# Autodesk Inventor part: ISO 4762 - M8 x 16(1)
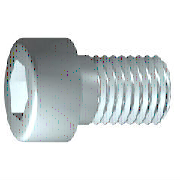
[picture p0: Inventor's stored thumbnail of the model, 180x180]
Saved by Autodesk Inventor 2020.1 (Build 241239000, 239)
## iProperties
Created: 2019-01
Part Number: ISO 4762 - M8 x 16(1)
Material: Edelstahl, 440C
Description: Innensechskantschraube
Document SubType Name: Modeling
Standard: ISO 4762
Designer: lutzd
Standard Revision: Fourth edition 2004-03-01
Standards Organization: ISO
Language: de-DE
Size Designation: M8 x 16
Categories: <MemberInstance><Categories><Category DisplayName="Verbindungselemente" InternalName="e4da775c-781d-43d5-af7c-5136215cf5a6" Mnemonic="FSTN"><Category DisplayNam
Mass: 13.2109 g
Surface Area: 10.585 cm^2
Volume: 1.70464 cm^3
Density: 7.75 g/cm^3
Appearance: Halbpoliert
IsCustomPart: 0
Author: lutzd
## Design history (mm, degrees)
body "Solid1"
sketch "Skizze1"
  geometry: L1 (-2, 0)-(16, 0); L2 (16, 0)-(16, 4); L3 (16, 4)-(3.125, 4); L4 (3.125, 4)-(2.358, 4); L5 (2.358, 4)-(0, 4); L6 (0, 4)-(0, 6.5); L7 (0, 6.5)-(-8, 6.5); L8 (-8, 6.5)-(-8, 3.464); L9 (-8, 3.464)-(-4, 3.464); L10 (-4, 3.464)-(-2, 0); L11 (-12.8, 0)-(20.8, 0) reference; L12 (0, -1.3)-(0, 7.8) reference; L13 (3.125, 4)-(0, 4)
  constraints: 22 end point, 6 parallel, 2 collinear, 2 perpendicular, 1 horizontal, 1 point on line
  dimensions: "d1" = 12.875 distance from line of L3.end L2 (= GEL); "d2" = 0.76691 distance of L4.end L3.end (computed from GAL); "d3" = 8 distance between parallel lines of L8 L6 (= KOH); "d4" = 4 distance of L8.end L9.end (= INTI); "d5" = 60 deg angle of L10 L1; "d6" = 8 diameter of L3 L1 (= GD); "d7" = 8 diameter of L5 L1 (= BDM); "d8" = 6.9282 diameter of L9 L1 (= 1.1547 x SW); "d9" = 13 diameter of L7 L1 (= KOD); "d26" = 16 distance between parallel lines of L12 L2 (= NLG)
workplane "Work Plane1"
fillet "Fillet2" dims "d30" = 0.1 (= R)
revolve "Körper" stored, may be unused: angle "d10" = 90 deg
sketch "Skizze2"
  geometry: L1 (0, -9.1)-(0, 9.1) reference; L2 (-9.1, 0)-(9.1, 0) reference; L3 (3.464, 0)-(1.732, -3); L4 (1.732, -3)-(-1.732, -3); L5 (-1.732, -3)-(-3.464, 0); L6 (-3.464, 0)-(-1.732, 3); L7 (-1.732, 3)-(1.732, 3); L8 (1.732, 3)-(3.464, 0); 2 further points
  constraints: 12 end point, 1 coincident, 1 horizontal alignment, 1 point on line, 12 other
extrude "Loch" join sketch "Skizze2" stored distance "d11" = 10; taper "d12" = 0 deg
fillet "Rundung1" dims "d17" = 0.8 (= RR)
feature "Gewinde" dims "d13" = 12.875 (= GEL), "d14" = 0
chamfer "Fase1" distance "d15" = 0.76681 (= -0.5 x SPD + 0.5 x GD); stored, may be unused: second distance "d16" = 0.76681 (= GUL), angle "d27" = 45 deg
other parameters: "GD" = 8 [user parameter; used in 2 equation terms], "NLG" = 16 [user parameter; used in 1 equation term], "GEL" = 12.875 [user parameter; used in 2 equation terms], "KOD" = 13 [user parameter; used in 1 equation term], "KOH" = 8 [user parameter; used in 1 equation term], "INTI" = 4 [user parameter; used in 1 equation term], "GAL" = 0.76681 (= 0.61345 x PTC) [user parameter; used in 1 equation term], "GUL" = 0.76681 (= 0.61345 x PTC) [user parameter; used in 1 equation term], "BDM" = 8 (= NND) [user parameter; used in 1 equation term], "SW" = 6 [user parameter; used in 2 equation terms], "RR" = 0.8 [user parameter; used in 1 equation term], "SPD" = 6.46637 (= NND - 1.2269 x PTC) [user parameter; used in 1 equation term], "d19" = 0, "d28" = 0, "d29" = 0, "R" = 0.1 [user parameter; used in 1 equation term], "TOA" = 30 deg [user parameter], "GD1" = 6.46637 (= THREADDIA - 1.2269 x PTC) [user parameter], "THREADDIA" = 8 [user parameter; used in 1 equation term], "FAWI" = 45 deg [user parameter], "TPU" = 8 (computed from PTC) [user parameter], "PTC" = 1.25 [user parameter; used in 5 equation terms], "NND" = 8 [user parameter; used in 2 equation terms], "E0" = 6.93 (= 1.155 x SW) [user parameter]
